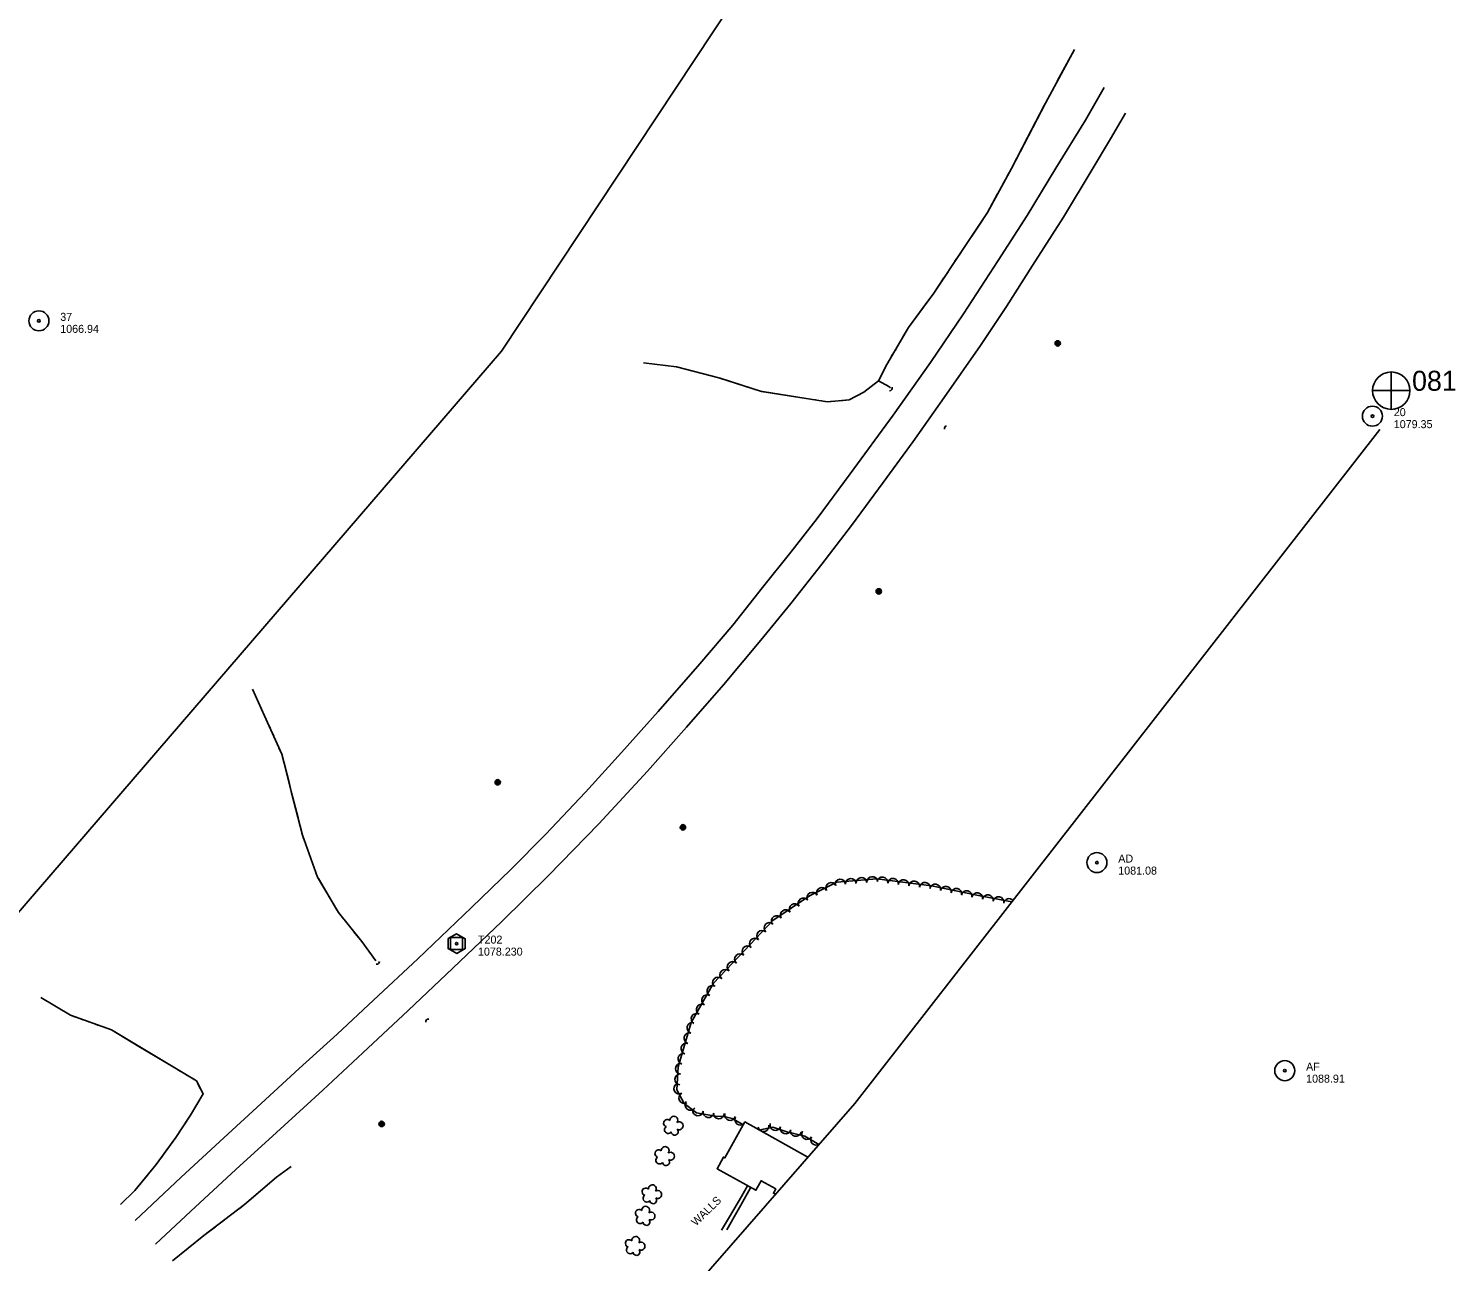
# Model space of a CAD drawing. Extents: x 296021 to 298261, y 27813 to 30404.
# Drawn here: x 296557 to 297626, y 28840 to 29764 of the extents above; entities that cross this region are included whole.
import ezdxf

# ---------------------------------------------------------------- set-up
doc = ezdxf.new("R2010")
doc.units = 0
for name, color, linetype in [('Level 11', 7, 'Continuous'), ('Level 12', 7, 'Continuous'), ('Level 14', 7, 'Continuous'), ('Level 15', 7, 'Continuous'), ('Level 18', 7, 'Continuous'), ('Level 19', 7, 'Continuous'), ('Level 4', 7, 'Continuous'), ('Level 5', 7, 'Continuous'), ('Level 6', 7, 'Continuous')]:
    doc.layers.add(name, color=color, linetype=linetype)

msp = doc.modelspace()

# ---------------------------------------------------------------- linework, layer by layer
at = {"layer": 'Level 11'}
for points in [[(296636.5, 28870.5), (296671, 28902.8), (296703, 28932.3), (296731, 28958.1), (296759.4, 28984.2), (296787.8, 29010), (296815.2, 29035.6), (296848.2, 29066.5), (296888.5, 29104.9), (296917.9, 29133.5), (296943.9, 29159.6), (296973.9, 29191.3), (297001, 29221), (297028.5, 29251.9), (297059.6, 29287.6), (297084.3, 29316.4), (297106.7, 29344.6), (297127.9, 29371.2), (297147.5, 29396.4), (297172.3, 29429.8), (297204.5, 29473.9), (297232.6, 29513.2), (297257.4, 29549.8), (297283.3, 29589.8), (297304.9, 29623.5), (297326.6, 29659), (297348.7, 29694.9), (297362.7, 29719.4)], [(296651.6, 28852.8), (296678.1, 28877.5), (296712, 28908.7), (296742.3, 28936.3), (296777, 28968.2), (296810.9, 28999.6), (296841.1, 29027.8), (296874.5, 29059.4), (296910.9, 29094.3), (296946.3, 29129), (296984.1, 29167.7), (297020.4, 29207.1), (297049.7, 29240), (297077.3, 29271.9), (297105.3, 29305.2), (297128, 29332.7), (297151.1, 29362.1), (297173.3, 29391.1), (297197.1, 29423.4), (297219.6, 29454.2), (297242.9, 29487), (297270, 29526.1), (297289.5, 29555.3), (297309, 29585.9), (297332.3, 29622.2), (297353.7, 29658), (297367.5, 29680.9), (297378.6, 29700.2)]]:
    msp.add_lwpolyline(points, dxfattribs=at)
at = {"layer": 'Level 12'}
msp.add_lwpolyline([(297140.7, 28918), (297093.5, 28944.3), (297078.5, 28917.3), (297077.4, 28917.9), (297072.6, 28909.2), (297101.7, 28893.1), (297105.6, 28900.2), (297116.6, 28894.1), (297114.8, 28890.9), (297116.3, 28890.1)], dxfattribs=at)
at = {"layer": 'Level 14'}
for centre, radius in [((297327.9, 29527.6), 2.02), ((297327.9, 29527.6), 1.52), ((297327.9, 29527.6), 1.01), ((297327.9, 29527.6), 0.502), ((297193.8, 29341.8), 2.02), ((297193.8, 29341.9), 1.52), ((297193.8, 29341.8), 1.01), ((297193.8, 29341.8), 0.502), ((296908.2, 29198.8), 2.02), ((296908.2, 29198.8), 1.52), ((296908.2, 29198.8), 1.01), ((296908.2, 29198.8), 0.502), ((297047, 29165), 2.02), ((297047, 29165), 1.52), ((297047, 29164.9), 1.01), ((297047, 29165), 0.502), ((296821.2, 28942.8), 2.02), ((296821.2, 28942.8), 1.52), ((296821.2, 28942.8), 1.01), ((296821.2, 28942.8), 0.502)]:
    msp.add_circle(centre, radius, dxfattribs=at)
at = {"layer": 'Level 15'}
for points in [[(297076, 28863.2), (297082, 28873.1), (297091, 28888.4), (297095.5, 28896.5)], [(297079.9, 28863.5), (297085.4, 28873.2), (297090.3, 28881.8), (297097.6, 28894.8)]]:
    msp.add_lwpolyline(points, dxfattribs=at)
for centre, radius, start, end in [((297201.9, 29494.2), 2.01, 268.3896, 14.6291), ((297244.8, 29463.9), 1.87, 93.9657, 200.2052), ((296817.6, 29064.4), 1.91, 256.7451, 2.9847), ((296856.2, 29019.3), 2.01, 79.7779, 186.0175)]:
    msp.add_arc(centre, radius, start, end, dxfattribs=at)
at = {"layer": 'Level 18'}
for points in [[(297293.5, 29109.3), (297269.8, 29113.6), (297233.3, 29121.2), (297192.4, 29126.4), (297162.4, 29124), (297141.8, 29113.6), (297114.3, 29095.3), (297088.6, 29068), (297070, 29048.3), (297053.1, 29018.7), (297043.4, 28985.5), (297042.4, 28968.3), (297047.9, 28958), (297057.3, 28951), (297071.3, 28948.7), (297077.8, 28948.4), (297083.9, 28946.8), (297092.5, 28942.1)], [(297103.8, 28938.2), (297114.3, 28940.3), (297124.9, 28936.9), (297138.4, 28933.7), (297148.8, 28927.3)]]:
    msp.add_lwpolyline(points, dxfattribs=at)
for centre, radius, start, end in [((297158.3, 29119.6), 4.02, 26.815, 206.7997), ((297164.9, 29122.1), 4.02, 4.631, 184.6157), ((297172.9, 29122.7), 4.02, 4.631, 184.6157), ((297180.9, 29123.4), 4.02, 4.631, 184.6157), ((297188.9, 29124), 4.02, 4.631, 184.6157), ((297196.5, 29123.8), 4.02, 352.6562, 172.6409), ((297204.5, 29122.7), 4.02, 352.6562, 172.6409), ((297212.4, 29121.7), 4.02, 352.6562, 172.6409), ((297220.4, 29120.7), 4.02, 352.6562, 172.6409), ((297228.4, 29119.7), 4.02, 352.6562, 172.6409), ((297236.1, 29118.4), 4.02, 348.3557, 168.3404), ((297137.4, 29108.1), 4.02, 33.6246, 213.6093), ((297143.9, 29112.3), 4.02, 26.815, 206.7997), ((297151.1, 29115.9), 4.02, 26.815, 206.7997), ((297244, 29116.8), 4.02, 348.3557, 168.3404), ((297251.9, 29115.2), 4.02, 348.3557, 168.3404), ((297259.7, 29113.5), 4.02, 348.3557, 168.3404), ((297267.6, 29111.9), 4.02, 348.3557, 168.3404), ((297275.6, 29110.4), 4.02, 349.7968, 169.7815), ((297283.5, 29109), 4.02, 349.7968, 169.7815), ((297124, 29099.2), 4.02, 33.6246, 213.6093), ((297130.7, 29103.7), 4.02, 33.6246, 213.6093), ((297291.4, 29107.6), 4.02, 42.8882, 169.7815), ((297111.8, 29089.6), 4.02, 46.6878, 226.6725), ((297117.3, 29094.8), 4.02, 33.6246, 213.6093), ((297100.8, 29077.9), 4.02, 46.6878, 226.6725), ((297106.3, 29083.8), 4.02, 46.6878, 226.6725), ((297089.8, 29066.2), 4.02, 46.7821, 226.7668), ((297095.3, 29072.1), 4.02, 46.6878, 226.6725), ((297078.8, 29054.5), 4.02, 46.7821, 226.7668), ((297084.3, 29060.4), 4.02, 46.7821, 226.7668), ((297073.3, 29048.7), 4.02, 46.7821, 226.7668), ((297065.1, 29035.5), 4.02, 60.2446, 240.2293), ((297069.1, 29042.5), 4.02, 60.2446, 240.2293), ((297061.1, 29028.5), 4.02, 60.2446, 240.2293), ((297054.1, 29014.7), 4.02, 73.7412, 253.7258), ((297057.2, 29021.5), 4.02, 60.2446, 240.2293), ((297051.9, 29007), 4.02, 73.7412, 253.7258), ((297047.4, 28991.5), 4.02, 73.7412, 253.7258), ((297049.6, 28999.2), 4.02, 73.7412, 253.7258), ((297045.5, 28984.2), 4.02, 86.6022, 266.5869), ((297044.3, 28969.3), 4.02, 117.981, 297.9656), ((297045, 28976.2), 4.02, 86.6022, 266.5869), ((297048, 28962.2), 4.02, 117.981, 297.9656), ((297052.6, 28957.1), 4.02, 143.3213, 323.3059), ((297058.3, 28952.9), 4.02, 170.6364, 350.6211), ((297066.2, 28951.6), 4.02, 170.6364, 350.6211), ((297035.3, 28943.4), 2.78, 45.6375, 253.4105), ((297036, 28938.4), 2.78, 122.3145, 323.3255), ((297040.2, 28945.6), 2.97, 322.6666, 183.9005), ((297044.2, 28941.4), 2.97, 240.3174, 123.2907), ((297073.9, 28950.7), 4.02, 177.9619, 357.9466), ((297082.3, 28949.4), 4.02, 164.4278, 344.4124), ((297090, 28945.9), 4.02, 152.0039, 313.8449), ((297107.4, 28941.1), 4.03, 250.385, 10.8864), ((297116.3, 28941.9), 4.03, 162.4821, 342.4668), ((297124, 28939.4), 4.03, 162.4821, 342.4668), ((297040.8, 28937), 2.61, 185.0226, 42.9552), ((297107.4, 28941.1), 4.03, 190.9017, 231.4629), ((297131.6, 28937.5), 4.03, 166.5582, 346.5429), ((297140, 28935.2), 4.03, 148.2375, 328.2222), ((297146.8, 28931), 4.03, 148.2375, 302.5281), ((297028.8, 28920.6), 2.78, 45.6375, 253.4105), ((297033.7, 28922.8), 2.97, 322.6666, 183.9005), ((297037.7, 28918.6), 2.97, 240.3174, 123.2907), ((297029.5, 28915.6), 2.78, 122.3145, 323.3255), ((297034.3, 28914.2), 2.61, 185.0226, 42.9552), ((297019.2, 28892), 2.78, 45.6375, 253.4105), ((297019.9, 28887), 2.78, 122.3145, 323.3255), ((297024.1, 28894.2), 2.97, 322.6666, 183.9005), ((297024.7, 28885.6), 2.61, 185.0226, 42.9552), ((297028.1, 28889.9), 2.97, 240.3174, 123.2907), ((297014.2, 28875.9), 2.78, 45.6375, 253.4105), ((297019.1, 28878.1), 2.97, 322.6666, 183.9005), ((297023.1, 28873.8), 2.97, 240.3174, 123.2907), ((297014.9, 28870.9), 2.78, 122.3145, 323.3255), ((297019.7, 28869.4), 2.61, 185.0226, 42.9552), ((297006.7, 28853.3), 2.78, 45.6375, 253.4105), ((297011.6, 28855.5), 2.97, 322.6666, 183.9005), ((297007.4, 28848.3), 2.78, 122.3145, 323.3255), ((297012.2, 28846.9), 2.61, 185.0226, 42.9552), ((297015.6, 28851.2), 2.97, 240.3174, 123.2907)]:
    msp.add_arc(centre, radius, start, end, dxfattribs=at)
at = {"layer": 'Level 19'}
for points in [[(297340.4, 29747.9), (297318.8, 29707.6), (297293.2, 29658.7), (297275.4, 29625.7), (297257.2, 29598.6), (297235, 29565.2), (297216, 29539.5), (297199.9, 29511.8), (297193.7, 29499.5), (297201.3, 29495.2), (297202.6, 29494.2)], [(297340.4, 29747.9), (297327.5, 29724)], [(297320.5, 29710.8), (297319.6, 29709.1)], [(297323.1, 29715.7), (297322.2, 29714.1)], [(297325.8, 29720.7), (297324.9, 29719)], [(297317.8, 29705.8), (297305.3, 29681.8)], [(297305.3, 29681.8), (297293.2, 29658.7), (297292.7, 29657.7)], [(297288.3, 29649.5), (297287.4, 29647.9)], [(297290.9, 29654.4), (297290.1, 29652.8)], [(297282.9, 29639.6), (297275.4, 29625.7), (297269.1, 29616.3)], [(297285.6, 29644.6), (297284.7, 29642.9)], [(297269.1, 29616.3), (297257.2, 29598.6), (297254, 29593.8)], [(297248.8, 29586), (297247.8, 29584.4)], [(297251.9, 29590.7), (297250.9, 29589.1)], [(297242.6, 29576.7), (297235, 29565.2), (297227, 29554.4)], [(297245.7, 29581.3), (297244.7, 29579.8)], [(297227, 29554.4), (297216, 29539.5), (297211.7, 29532.1)], [(297209.8, 29528.9), (297208.8, 29527.3)], [(297204.1, 29519.2), (297203.2, 29517.6)], [(297207, 29524), (297206, 29522.4)], [(297193.7, 29499.5), (297182.7, 29491), (297171.5, 29485.3), (297155.3, 29483.8), (297106, 29491.6), (297074, 29501.8), (297042.1, 29510.1), (297017.4, 29513.1)], [(297050.3, 29508), (297042.1, 29510.1), (297017.4, 29513.1)], [(297201.3, 29514.3), (297199.9, 29511.8), (297193.7, 29499.5), (297201.3, 29495.2), (297202.6, 29494.2)], [(297057, 29506.2), (297054.7, 29506.8)], [(297063.6, 29504.5), (297061.4, 29505.1)], [(297070.3, 29502.7), (297068.1, 29503.3)], [(297106.6, 29491.5), (297106, 29491.6), (297074.8, 29501.5)], [(297193.7, 29499.5), (297182.7, 29491), (297171.5, 29485.3), (297164.6, 29484.6)], [(297139.5, 29486.3), (297106.6, 29491.5)], [(297146.4, 29485.2), (297144.1, 29485.5)], [(297153.2, 29484.1), (297150.9, 29484.5)], [(297160, 29484.2), (297157.7, 29484)], [(296816.8, 29064.9), (296806.3, 29079.4), (296788.8, 29101.2), (296773.2, 29127.8), (296761.8, 29159.1), (296753.5, 29191.9), (296746.4, 29219.9), (296733.5, 29248.6), (296724.5, 29268.6)], [(296735.7, 29243.6), (296733.5, 29248.6), (296724.5, 29268.6)], [(296738, 29238.5), (296737.3, 29240.2)], [(296740.3, 29233.3), (296739.6, 29235)], [(296742.7, 29228.2), (296741.9, 29229.9)], [(296751.8, 29198.6), (296746.4, 29219.9), (296744.2, 29224.7)], [(296758.5, 29172.1), (296753.5, 29191.9), (296751.8, 29198.6)], [(296759.9, 29166.6), (296759.5, 29168.4)], [(296761.3, 29161.1), (296760.8, 29162.9)], [(296763, 29155.7), (296762.4, 29157.5)], [(296773.9, 29126.6), (296773.2, 29127.8), (296764.3, 29152.2)], [(296787.7, 29103.1), (296773.9, 29126.6)], [(296791, 29098.5), (296789.8, 29100)], [(296794.5, 29094.1), (296793.3, 29095.5)], [(296798, 29089.7), (296796.9, 29091.1)], [(296816.8, 29064.9), (296806.3, 29079.4), (296800.4, 29086.7)], [(296625.4, 28882.5), (296636.1, 28892.9), (296652.2, 28912.3), (296666.9, 28932.7), (296677.9, 28949.4), (296687.5, 28965.4), (296682.4, 28975.1), (296618.8, 29013.2), (296587.9, 29024.2), (296565.8, 29037.6)], [(296591.7, 29022.8), (296587.9, 29024.2), (296565.8, 29037.6)], [(296597.6, 29020.8), (296595.6, 29021.5)], [(296603.4, 29018.7), (296601.5, 29019.4)], [(296609.2, 29016.6), (296607.3, 29017.3)], [(296639.3, 29000.9), (296618.8, 29013.2), (296613.1, 29015.2)], [(296665, 28985.5), (296639.3, 29000.9)], [(296670.3, 28982.3), (296668.5, 28983.4)], [(296675.6, 28979.1), (296673.8, 28980.2)], [(296676.4, 28947.1), (296677.9, 28949.4), (296687.5, 28965.4), (296683.5, 28972.9)], [(296680.9, 28976), (296679.2, 28977)], [(296659.5, 28922.4), (296666.9, 28932.7), (296676.4, 28947.1)], [(296648.3, 28907.6), (296649.6, 28909.2)], [(296652.2, 28912.4), (296653.4, 28914.1)], [(296655.9, 28917.4), (296657.1, 28919.1)], [(296664.4, 28840.2), (296688, 28859.1), (296718.5, 28882.4), (296742.4, 28902.9), (296753.3, 28910.8)], [(296721.3, 28884.9), (296742.4, 28902.9), (296753.3, 28910.8)], [(296625.4, 28882.5), (296636.1, 28892.9), (296645.7, 28904.5)], [(296714.7, 28879.5), (296717, 28881.2)], [(296664.4, 28840.2), (296688, 28859.1), (296696.7, 28865.7)], [(296701.2, 28869.2), (296703.4, 28870.9)], [(296708, 28874.3), (296710.2, 28876.1)]]:
    msp.add_lwpolyline(points, dxfattribs=at)
at = {"layer": 'Level 4'}
for p, q in [((297577.8, 29506.2), (297577.8, 29478.4)), ((297563.9, 29492.2), (297591.8, 29492.2))]:
    msp.add_line(p, q, dxfattribs=at)
for points in [[(296492.9, 29036.3), (296910.9, 29521.9), (297186.2, 29936.9)], [(297569.3, 29463.2), (297175.8, 28958.2), (296866.7, 28604.1)]]:
    msp.add_lwpolyline(points, dxfattribs=at)
msp.add_circle((297577.9, 29492.2), 14, dxfattribs=at)
at = {"layer": 'Level 5'}
for points in [[(296871, 29081.6), (296871, 29074.2), (296877.5, 29070.5), (296883.9, 29074.2), (296883.9, 29081.5), (296877.3, 29085.2)], [(296872.9, 29073.4), (296872.9, 29082.4), (296881.9, 29082.4), (296881.9, 29073.4)]]:
    msp.add_lwpolyline(points, close=True, dxfattribs=at)
msp.add_circle((296877.4, 29077.9), 0.871, dxfattribs=at)
at = {"layer": 'Level 6'}
for centre, radius in [((296564.3, 29544.5), 7.5), ((296564.3, 29544.5), 0.96), ((297563.8, 29473.1), 7.5), ((297563.8, 29473.1), 0.96), ((297357.3, 29138.6), 7.5), ((297357.3, 29138.6), 0.96), ((297498.1, 28982.7), 7.5), ((297498.1, 28982.7), 0.96)]:
    msp.add_circle(centre, radius, dxfattribs=at)

# ---------------------------------------------------------------- texts
at = {"layer": 'Level 15'}
msp.add_text('WALLS', height=6, rotation=44.2429, dxfattribs=at).set_placement((297056.8, 28865.9))
at = {"layer": 'Level 4'}
msp.add_text('081', height=15, dxfattribs=at).set_placement((297593.5, 29492.1))
at = {"layer": 'Level 5'}
for s, p in [('T202', (296893.4, 29077.9)), ('1078.230', (296893.4, 29068.9))]:
    msp.add_text(s, height=6, dxfattribs=at).set_placement(p)
at = {"layer": 'Level 6'}
for s, p in [('37', (296580.3, 29544.5)), ('1066.94', (296580.3, 29535.5)), ('20', (297579.8, 29473.1)), ('1079.35', (297579.8, 29464.1)), ('AD', (297373.3, 29138.6)), ('1081.08', (297373.3, 29129.6)), ('AF', (297514.1, 28982.7)), ('1088.91', (297514.1, 28973.7))]:
    msp.add_text(s, height=6, dxfattribs=at).set_placement(p)

doc.saveas('drawing.dxf')
